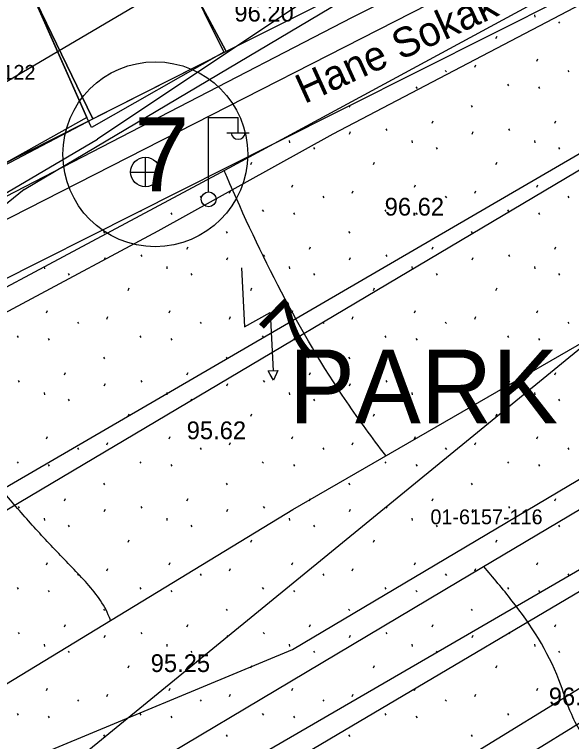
# Model space of a CAD drawing. Extents: x 412225 to 413380, y 4456471 to 4457189.
# Drawn here: x 412837.41 to 412875.09, y 4456673.13 to 4456722.27 of the extents above; entities that cross this region are included whole.
import ezdxf

# ---------------------------------------------------------------- set-up
doc = ezdxf.new("R2010")
doc.units = 0
for name, color, linetype in [('0_HALİHAZIR', 7, 'Continuous'), ('0_KADASTRO', 7, 'Continuous'), ('Level 28', 7, 'Continuous'), ('Level 41', 7, 'Continuous'), ('Level 54', 7, 'Continuous'), ('Level 58', 7, 'Continuous'), ('Level 62', 7, 'Continuous')]:
    doc.layers.add(name, color=color, linetype=linetype)

msp = doc.modelspace()

# ---------------------------------------------------------------- linework, layer by layer
at = {"layer": '0_HALİHAZIR'}
for p, q in [((412850.537, 4456710.308), (412850.537, 4456715.308)), ((412850.537, 4456715.308), (412852.537, 4456715.308)), ((412852.537, 4456714.308), (412852.537, 4456715.308)), ((412851.777, 4456714.268), (412853.277, 4456714.268)), ((412846.281, 4456710.619), (412846.281, 4456712.619)), ((412845.261, 4456711.609), (412847.261, 4456711.609))]:
    msp.add_line(p, q, dxfattribs=at)
for points in [[(413308.103, 4456965.941), (413265.175, 4456940.384), (413047.239, 4456812.664), (412821.475, 4456681.363)], [(412841.576, 4456665.003), (413057.926, 4456790.466), (413273.464, 4456916.652), (413307.769, 4456936.91)], [(412931.837, 4456800.178), (412903.863, 4456787.544), (412893.413, 4456782.904), (412892.513, 4456782.283), (412891.907, 4456781.457), (412891.837, 4456780.842), (412902.994, 4456756.704), (412906.93, 4456745.654), (412907.054, 4456744.017), (412906.977, 4456743.038), (412906.753, 4456742.155), (412906.55, 4456741.728), (412906.154, 4456741.055), (412879.555, 4456726.854), (412851.066, 4456711.433), (412824.165, 4456697.062), (412814.561, 4456691.644)], [(412816.025, 4456699.683), (412835.485, 4456709.295), (412860.277, 4456722.092), (412890.448, 4456737.159), (412902.212, 4456743.322), (412902.198, 4456743.87), (412894.314, 4456761.759), (412893.593, 4456762.996), (412893.507, 4456763.111), (412860.542, 4456748.553), (412831.808, 4456733.953), (412813.075, 4456726.17)], [(412858.966, 4456714.206), (412889.238, 4456730.065), (412907.414, 4456740.616), (412908.265, 4456741.87), (412908.952, 4456743.506), (412909.302, 4456744.253), (412909.611, 4456744.779), (412927.708, 4456755.383), (412944.2, 4456762.714), (412944.939, 4456762.704), (412945.604, 4456762.403), (412952.812, 4456743.534), (412954.202, 4456739.684), (412953.996, 4456738.954), (412951.842, 4456736.97)], [(412812.813, 4456662.398), (412856.245, 4456688.806), (412912.334, 4456721.138), (412944.097, 4456732.816)], [(412813.007, 4456650.071), (412835.489, 4456664.933), (412867.464, 4456683.962), (412901.181, 4456703.969), (412934.85, 4456721.065), (412956.754, 4456731.07), (412958.117, 4456731.459), (412959.035, 4456731.634), (412960.277, 4456731.39), (412961.32, 4456730.801), (412962.336, 4456729.858), (412972.363, 4456705.953), (412988.995, 4456670.284), (413003.917, 4456634.999), (413014.424, 4456609.495), (413014.707, 4456606.962), (413014.677, 4456605.697), (413014.483, 4456604.379), (413013.724, 4456603.316), (412984.218, 4456588.075)], [(412815.749, 4456691.343), (412828.75, 4456697.822), (412847.13, 4456707.658), (412858.966, 4456714.206)], [(412852.778, 4456705.155), (412852.971, 4456701.157), (412854.714, 4456702.136), (412854.91, 4456698.174)]]:
    msp.add_lwpolyline(points, dxfattribs=at)
for points in [[(412838.663, 4456723.568), (412847.549, 4456727.851), (412851.572, 4456719.726), (412842.627, 4456714.626), (412842.316, 4456715.307)], [(412838.188, 4456724.641), (412842.316, 4456715.307), (412833.98, 4456710.678), (412829.754, 4456719.226)], [(412854.574, 4456698.18), (412855.23, 4456698.217), (412854.931, 4456697.544), (412854.716, 4456697.928)]]:
    msp.add_lwpolyline(points, close=True, dxfattribs=at)
for centre, radius in [((412846.266, 4456711.627), 1), ((412850.548, 4456709.783), 0.5)]:
    msp.add_circle(centre, radius, dxfattribs=at)
msp.add_arc((412852.537, 4456714.311), 0.474, 184.8384, 355.1464, dxfattribs=at)
for points in [[(412862.546, 4456692.438), (412862.521, 4456692.47), (412859.884, 4456696.083), (412851.773, 4456711.318), (412851.599, 4456711.722)], [(412843.912, 4456681.307), (412843.757, 4456681.694), (412842.081, 4456684.075), (412840.012, 4456686.241), (412837.991, 4456688.456), (412836.059, 4456690.749), (412834.248, 4456693.133), (412832.578, 4456695.619), (412831.011, 4456698.177), (412829.858, 4456700.104)], [(412954.779, 4456612.553), (412952.206, 4456613.697), (412941.009, 4456618.727), (412920.288, 4456630.573), (412911.175, 4456637.709), (412908.09, 4456640.597), (412896.792, 4456650.717), (412890.704, 4456656.374), (412889.418, 4456657.685), (412876.396, 4456672.773), (412875.794, 4456673.634), (412875.1, 4456674.94), (412874.235, 4456677.292), (412871.061, 4456682.644), (412869.151, 4456684.963)]]:
    msp.add_spline(points, degree=3, dxfattribs=at)
at = {"layer": '0_KADASTRO'}
for points in [[(412758.558, 4456668.786), (412808.977, 4456694.209), (412902.634, 4456741.974), (412909.074, 4456745.179), (412943.419, 4456762.272), (412949.024, 4456765.062), (412952.615, 4456766.849), (412963.581, 4456772.307), (412985.511, 4456783.221), (412985.536, 4456782.611), (412987.65, 4456731.4), (412981.45, 4456727.59), (412970.633, 4456720.947), (412967.171, 4456718.821), (412964.24, 4456717.02), (412920.19, 4456689.98), (412911.66, 4456684.75), (412892.499, 4456672.986), (412877.7, 4456663.9), (412867.363, 4456657.565), (412824.012, 4456630.971), (412807.183, 4456620.644)], [(412846.893, 4456728.773), (412852.747, 4456731.593), (412855.714, 4456733.022), (412860.243, 4456724.055), (412851.736, 4456719.768), (412851.687, 4456719.86), (412847.536, 4456727.578)], [(412838.173, 4456724.573), (412840.926, 4456725.899), (412846.893, 4456728.773), (412847.536, 4456727.578), (412851.687, 4456719.86), (412851.736, 4456719.768), (412842.722, 4456715.224), (412842.675, 4456715.32), (412838.877, 4456723.125)], [(412829.278, 4456720.289), (412834.972, 4456723.032), (412838.173, 4456724.573), (412838.877, 4456723.125), (412842.675, 4456715.32), (412842.722, 4456715.224), (412834.005, 4456710.64), (412833.943, 4456710.767), (412829.896, 4456719.028)]]:
    msp.add_lwpolyline(points, close=True, dxfattribs=at)
at = {"layer": 'Level 28'}
for p, q in [((412901.361, 4456744.693), (412851.736, 4456719.768)), ((412854.878, 4456713.513), (412901.65, 4456737.005)), ((412851.736, 4456719.768), (412806.83, 4456697.135)), ((412803.636, 4456687.687), (412854.887, 4456713.517)), ((412917.79, 4456702.575), (412795.286, 4456627.414))]:
    msp.add_line(p, q, dxfattribs=at)
at = {"layer": 'Level 41'}
for p, q in [((412872.587, 4456722.26), (412872.605, 4456722.1)), ((412874.217, 4456721.79), (412874.287, 4456721.683)), ((412869.98, 4456720.646), (412870.052, 4456720.806)), ((412872.752, 4456719.116), (412872.822, 4456719.276)), ((412866.554, 4456718.5), (412866.625, 4456718.394)), ((412868.542, 4456718.708), (412868.613, 4456718.868)), ((412874.847, 4456718.5), (412874.918, 4456718.394)), ((412870.762, 4456717.571), (412870.833, 4456717.464)), ((412864.568, 4456717.379), (412864.639, 4456717.272)), ((412872.861, 4456717.379), (412872.932, 4456717.272)), ((412860.026, 4456716.098), (412860.084, 4456716.011)), ((412868.306, 4456716.118), (412868.377, 4456716.011)), ((412865.665, 4456714.925), (412865.736, 4456715.084)), ((412873.958, 4456714.925), (412874.029, 4456715.084)), ((412862.536, 4456714.541), (412862.607, 4456714.434)), ((412870.829, 4456714.541), (412870.9, 4456714.434)), ((412860.071, 4456714.196), (412860.143, 4456714.356)), ((412868.364, 4456714.196), (412868.436, 4456714.356)), ((412856.001, 4456713.75), (412856.019, 4456713.59)), ((412864.294, 4456713.75), (412864.312, 4456713.59)), ((412872.587, 4456713.75), (412872.605, 4456713.59)), ((412857.631, 4456713.28), (412857.701, 4456713.173)), ((412865.924, 4456713.28), (412865.994, 4456713.173)), ((412874.217, 4456713.28), (412874.287, 4456713.173)), ((412853.394, 4456712.136), (412853.466, 4456712.296)), ((412861.687, 4456712.136), (412861.759, 4456712.296)), ((412869.98, 4456712.136), (412870.052, 4456712.296)), ((412856.166, 4456710.606), (412856.236, 4456710.766)), ((412864.459, 4456710.606), (412864.529, 4456710.766)), ((412872.752, 4456710.606), (412872.822, 4456710.766)), ((412851.956, 4456710.198), (412852.027, 4456710.358)), ((412860.249, 4456710.198), (412860.32, 4456710.358)), ((412868.542, 4456710.198), (412868.613, 4456710.358)), ((412849.968, 4456709.99), (412850.039, 4456709.884)), ((412858.261, 4456709.99), (412858.332, 4456709.884)), ((412866.554, 4456709.99), (412866.625, 4456709.884)), ((412874.847, 4456709.99), (412874.918, 4456709.884)), ((412854.176, 4456709.061), (412854.247, 4456708.954)), ((412862.469, 4456709.061), (412862.54, 4456708.954)), ((412870.762, 4456709.061), (412870.833, 4456708.954)), ((412845.924, 4456709), (412845.954, 4456708.954)), ((412847.982, 4456708.869), (412848.053, 4456708.762)), ((412856.275, 4456708.869), (412856.346, 4456708.762)), ((412864.568, 4456708.869), (412864.639, 4456708.762)), ((412872.861, 4456708.869), (412872.932, 4456708.762)), ((412843.427, 4456707.608), (412843.498, 4456707.501)), ((412851.72, 4456707.608), (412851.791, 4456707.501)), ((412860.013, 4456707.608), (412860.084, 4456707.501)), ((412868.306, 4456707.608), (412868.377, 4456707.501)), ((412849.079, 4456706.415), (412849.15, 4456706.574)), ((412857.372, 4456706.415), (412857.443, 4456706.574)), ((412865.665, 4456706.415), (412865.736, 4456706.574)), ((412873.958, 4456706.415), (412874.029, 4456706.574)), ((412843.485, 4456705.686), (412843.557, 4456705.846)), ((412845.95, 4456706.031), (412846.021, 4456705.924)), ((412851.778, 4456705.686), (412851.85, 4456705.846)), ((412854.243, 4456706.031), (412854.314, 4456705.924)), ((412860.071, 4456705.686), (412860.143, 4456705.846)), ((412862.536, 4456706.031), (412862.607, 4456705.924)), ((412868.364, 4456705.686), (412868.436, 4456705.846)), ((412870.829, 4456706.031), (412870.9, 4456705.924)), ((412839.415, 4456705.24), (412839.433, 4456705.08)), ((412847.708, 4456705.24), (412847.726, 4456705.08)), ((412856.001, 4456705.24), (412856.019, 4456705.08)), ((412864.294, 4456705.24), (412864.312, 4456705.08)), ((412872.587, 4456705.24), (412872.605, 4456705.08)), ((412841.045, 4456704.77), (412841.115, 4456704.663)), ((412849.338, 4456704.77), (412849.408, 4456704.663)), ((412857.631, 4456704.77), (412857.701, 4456704.663)), ((412865.924, 4456704.77), (412865.994, 4456704.663)), ((412874.217, 4456704.77), (412874.287, 4456704.663)), ((412845.101, 4456703.626), (412845.173, 4456703.786)), ((412853.394, 4456703.626), (412853.466, 4456703.786)), ((412861.687, 4456703.626), (412861.759, 4456703.786)), ((412869.98, 4456703.626), (412870.052, 4456703.786)), ((412839.58, 4456702.096), (412839.65, 4456702.256)), ((412847.873, 4456702.096), (412847.943, 4456702.256)), ((412856.166, 4456702.096), (412856.236, 4456702.256)), ((412864.459, 4456702.096), (412864.529, 4456702.256)), ((412872.752, 4456702.096), (412872.822, 4456702.256)), ((412843.663, 4456701.688), (412843.734, 4456701.848)), ((412851.956, 4456701.688), (412852.027, 4456701.848)), ((412860.249, 4456701.688), (412860.32, 4456701.848)), ((412868.542, 4456701.688), (412868.613, 4456701.848)), ((412841.675, 4456701.48), (412841.746, 4456701.374)), ((412849.968, 4456701.48), (412850.039, 4456701.374)), ((412858.261, 4456701.48), (412858.332, 4456701.374)), ((412866.554, 4456701.48), (412866.625, 4456701.374)), ((412874.847, 4456701.48), (412874.918, 4456701.374)), ((412837.59, 4456700.551), (412837.661, 4456700.444)), ((412839.689, 4456700.359), (412839.76, 4456700.252)), ((412845.883, 4456700.551), (412845.954, 4456700.444)), ((412847.982, 4456700.359), (412848.053, 4456700.252)), ((412854.176, 4456700.551), (412854.247, 4456700.444)), ((412856.275, 4456700.359), (412856.346, 4456700.252)), ((412862.469, 4456700.551), (412862.54, 4456700.444)), ((412864.568, 4456700.359), (412864.639, 4456700.252)), ((412870.762, 4456700.551), (412870.833, 4456700.444)), ((412872.861, 4456700.359), (412872.932, 4456700.252)), ((412843.427, 4456699.098), (412843.498, 4456698.991)), ((412851.72, 4456699.098), (412851.791, 4456698.991)), ((412860.013, 4456699.098), (412860.084, 4456698.991)), ((412868.306, 4456699.098), (412868.377, 4456698.991)), ((412840.786, 4456697.905), (412840.857, 4456698.064)), ((412849.079, 4456697.905), (412849.15, 4456698.064)), ((412857.372, 4456697.905), (412857.443, 4456698.064)), ((412865.665, 4456697.905), (412865.736, 4456698.064)), ((412873.958, 4456697.905), (412874.029, 4456698.064)), ((412837.657, 4456697.521), (412837.728, 4456697.414)), ((412843.485, 4456697.176), (412843.557, 4456697.336)), ((412845.95, 4456697.521), (412846.021, 4456697.414)), ((412851.778, 4456697.176), (412851.85, 4456697.336)), ((412854.243, 4456697.521), (412854.314, 4456697.414)), ((412860.071, 4456697.176), (412860.143, 4456697.336)), ((412862.536, 4456697.521), (412862.607, 4456697.414)), ((412868.364, 4456697.176), (412868.436, 4456697.336)), ((412870.829, 4456697.521), (412870.9, 4456697.414)), ((412839.415, 4456696.73), (412839.433, 4456696.57)), ((412847.708, 4456696.73), (412847.726, 4456696.57)), ((412856.001, 4456696.73), (412856.019, 4456696.57)), ((412864.294, 4456696.73), (412864.312, 4456696.57)), ((412872.587, 4456696.73), (412872.605, 4456696.57)), ((412841.045, 4456696.26), (412841.115, 4456696.153)), ((412849.338, 4456696.26), (412849.408, 4456696.153)), ((412857.631, 4456696.26), (412857.701, 4456696.153)), ((412865.924, 4456696.26), (412865.994, 4456696.153)), ((412874.217, 4456696.26), (412874.287, 4456696.153)), ((412845.101, 4456695.116), (412845.173, 4456695.276)), ((412853.394, 4456695.116), (412853.466, 4456695.276)), ((412861.687, 4456695.116), (412861.759, 4456695.276)), ((412869.98, 4456695.116), (412870.052, 4456695.276)), ((412839.58, 4456693.586), (412839.65, 4456693.746)), ((412843.663, 4456693.178), (412843.734, 4456693.338)), ((412847.873, 4456693.586), (412847.943, 4456693.746)), ((412851.956, 4456693.178), (412852.027, 4456693.338)), ((412856.166, 4456693.586), (412856.236, 4456693.746)), ((412860.249, 4456693.178), (412860.32, 4456693.338)), ((412864.459, 4456693.586), (412864.529, 4456693.746)), ((412868.542, 4456693.178), (412868.613, 4456693.338)), ((412872.752, 4456693.586), (412872.822, 4456693.746)), ((412841.675, 4456692.97), (412841.746, 4456692.864)), ((412849.968, 4456692.97), (412850.039, 4456692.864)), ((412858.261, 4456692.97), (412858.332, 4456692.864)), ((412866.554, 4456692.97), (412866.625, 4456692.864)), ((412874.847, 4456692.97), (412874.918, 4456692.864)), ((412837.59, 4456692.041), (412837.661, 4456691.934)), ((412839.689, 4456691.849), (412839.76, 4456691.742)), ((412845.883, 4456692.041), (412845.954, 4456691.934)), ((412847.982, 4456691.849), (412848.053, 4456691.742)), ((412854.176, 4456692.041), (412854.247, 4456691.934)), ((412856.275, 4456691.849), (412856.346, 4456691.742)), ((412862.469, 4456692.041), (412862.54, 4456691.934)), ((412864.568, 4456691.849), (412864.639, 4456691.742)), ((412870.762, 4456692.041), (412870.833, 4456691.934)), ((412872.861, 4456691.849), (412872.932, 4456691.742)), ((412843.427, 4456690.588), (412843.498, 4456690.481)), ((412851.72, 4456690.588), (412851.791, 4456690.481)), ((412860.013, 4456690.588), (412860.084, 4456690.481)), ((412868.306, 4456690.588), (412868.377, 4456690.481)), ((412840.786, 4456689.395), (412840.857, 4456689.554)), ((412849.079, 4456689.395), (412849.15, 4456689.554)), ((412857.372, 4456689.395), (412857.443, 4456689.554)), ((412865.665, 4456689.395), (412865.736, 4456689.554)), ((412873.958, 4456689.395), (412874.029, 4456689.554)), ((412837.657, 4456689.011), (412837.728, 4456688.904)), ((412845.95, 4456689.011), (412846.021, 4456688.904)), ((412854.243, 4456689.011), (412854.314, 4456688.904)), ((412862.536, 4456689.011), (412862.607, 4456688.904)), ((412870.829, 4456689.011), (412870.9, 4456688.904)), ((412843.485, 4456688.666), (412843.557, 4456688.826)), ((412851.778, 4456688.666), (412851.85, 4456688.826)), ((412860.071, 4456688.666), (412860.143, 4456688.826)), ((412868.364, 4456688.666), (412868.436, 4456688.826)), ((412839.415, 4456688.22), (412839.433, 4456688.06)), ((412847.708, 4456688.22), (412847.726, 4456688.06)), ((412856.001, 4456688.22), (412856.019, 4456688.06)), ((412864.294, 4456688.22), (412864.312, 4456688.06)), ((412872.587, 4456688.22), (412872.605, 4456688.06)), ((412841.045, 4456687.75), (412841.115, 4456687.643)), ((412849.338, 4456687.75), (412849.408, 4456687.643)), ((412857.631, 4456687.75), (412857.701, 4456687.643)), ((412865.924, 4456687.75), (412865.994, 4456687.643)), ((412874.217, 4456687.75), (412874.287, 4456687.643)), ((412845.101, 4456686.606), (412845.173, 4456686.766)), ((412853.394, 4456686.606), (412853.466, 4456686.766)), ((412861.687, 4456686.606), (412861.759, 4456686.766)), ((412869.98, 4456686.606), (412870.052, 4456686.766)), ((412839.58, 4456685.076), (412839.65, 4456685.236)), ((412847.873, 4456685.076), (412847.943, 4456685.236)), ((412856.166, 4456685.076), (412856.236, 4456685.236)), ((412864.459, 4456685.076), (412864.529, 4456685.236)), ((412872.752, 4456685.076), (412872.822, 4456685.236)), ((412843.663, 4456684.668), (412843.734, 4456684.828)), ((412851.956, 4456684.668), (412852.027, 4456684.828)), ((412860.249, 4456684.668), (412860.32, 4456684.828)), ((412868.542, 4456684.668), (412868.613, 4456684.828)), ((412841.675, 4456684.46), (412841.746, 4456684.354)), ((412849.968, 4456684.46), (412850.039, 4456684.354)), ((412858.261, 4456684.46), (412858.332, 4456684.354)), ((412866.554, 4456684.46), (412866.625, 4456684.354)), ((412874.847, 4456684.46), (412874.918, 4456684.354)), ((412837.59, 4456683.531), (412837.661, 4456683.424)), ((412845.883, 4456683.531), (412845.954, 4456683.424)), ((412854.176, 4456683.531), (412854.247, 4456683.424)), ((412862.469, 4456683.531), (412862.54, 4456683.424)), ((412870.762, 4456683.531), (412870.833, 4456683.424)), ((412839.689, 4456683.339), (412839.76, 4456683.232)), ((412847.982, 4456683.339), (412848.053, 4456683.232)), ((412856.275, 4456683.339), (412856.346, 4456683.232)), ((412864.568, 4456683.339), (412864.639, 4456683.232)), ((412872.861, 4456683.339), (412872.932, 4456683.232)), ((412843.427, 4456682.078), (412843.498, 4456681.971)), ((412851.72, 4456682.078), (412851.791, 4456681.971)), ((412860.013, 4456682.078), (412860.084, 4456681.971)), ((412868.306, 4456682.078), (412868.377, 4456681.971)), ((412840.786, 4456680.885), (412840.857, 4456681.044)), ((412849.079, 4456680.885), (412849.15, 4456681.044)), ((412857.372, 4456680.885), (412857.443, 4456681.044)), ((412865.665, 4456680.885), (412865.736, 4456681.044)), ((412873.958, 4456680.885), (412874.029, 4456681.044)), ((412837.657, 4456680.501), (412837.728, 4456680.394)), ((412843.485, 4456680.156), (412843.557, 4456680.316)), ((412845.95, 4456680.501), (412846.021, 4456680.394)), ((412851.778, 4456680.156), (412851.85, 4456680.316)), ((412854.243, 4456680.501), (412854.314, 4456680.394)), ((412860.071, 4456680.156), (412860.143, 4456680.316)), ((412862.536, 4456680.501), (412862.607, 4456680.394)), ((412868.364, 4456680.156), (412868.436, 4456680.316)), ((412870.829, 4456680.501), (412870.9, 4456680.394)), ((412839.415, 4456679.71), (412839.433, 4456679.55)), ((412847.708, 4456679.71), (412847.726, 4456679.55)), ((412856.001, 4456679.71), (412856.019, 4456679.55)), ((412864.294, 4456679.71), (412864.312, 4456679.55)), ((412872.587, 4456679.71), (412872.605, 4456679.55)), ((412841.045, 4456679.24), (412841.115, 4456679.133)), ((412849.338, 4456679.24), (412849.408, 4456679.133)), ((412857.631, 4456679.24), (412857.701, 4456679.133)), ((412865.924, 4456679.24), (412865.994, 4456679.133)), ((412874.217, 4456679.24), (412874.287, 4456679.133)), ((412845.101, 4456678.096), (412845.173, 4456678.256)), ((412853.394, 4456678.096), (412853.466, 4456678.256)), ((412861.687, 4456678.096), (412861.759, 4456678.256)), ((412869.98, 4456678.096), (412870.052, 4456678.256)), ((412839.58, 4456676.566), (412839.65, 4456676.726)), ((412847.873, 4456676.566), (412847.943, 4456676.726)), ((412856.166, 4456676.566), (412856.236, 4456676.726)), ((412864.459, 4456676.566), (412864.529, 4456676.726)), ((412872.752, 4456676.566), (412872.822, 4456676.726)), ((412843.663, 4456676.158), (412843.734, 4456676.318)), ((412851.956, 4456676.158), (412852.027, 4456676.318)), ((412860.249, 4456676.158), (412860.32, 4456676.318)), ((412868.542, 4456676.158), (412868.613, 4456676.318)), ((412841.675, 4456675.95), (412841.746, 4456675.844)), ((412849.968, 4456675.95), (412850.039, 4456675.844)), ((412858.261, 4456675.95), (412858.332, 4456675.844)), ((412866.554, 4456675.95), (412866.625, 4456675.844)), ((412837.59, 4456675.021), (412837.661, 4456674.914)), ((412839.689, 4456674.829), (412839.76, 4456674.722)), ((412845.883, 4456675.021), (412845.954, 4456674.914)), ((412847.982, 4456674.829), (412848.053, 4456674.722)), ((412854.176, 4456675.021), (412854.247, 4456674.914)), ((412856.275, 4456674.829), (412856.346, 4456674.722)), ((412862.469, 4456675.021), (412862.54, 4456674.914)), ((412864.568, 4456674.829), (412864.639, 4456674.722)), ((412870.762, 4456675.021), (412870.833, 4456674.914)), ((412843.427, 4456673.568), (412843.498, 4456673.461)), ((412851.72, 4456673.568), (412851.791, 4456673.461)), ((412860.013, 4456673.568), (412860.084, 4456673.461)), ((412868.306, 4456673.568), (412868.377, 4456673.461))]:
    msp.add_line(p, q, dxfattribs=at)
at = {"layer": 'Level 54'}
for p, q in [((412879.336, 4456738.107), (412843.025, 4456713.837)), ((412838.075, 4456710.447), (412777.393, 4456661.653)), ((412839.084, 4456669.826), (412887.855, 4456709.671)), ((412784.448, 4456649.562), (412856.216, 4456679.35))]:
    msp.add_line(p, q, dxfattribs=at)
for points in [[(412772.861, 4456680.089), (413040.614, 4456837.658)], [(412772.521, 4456650.705), (412780.988, 4456655.646), (413046.364, 4456813.097)], [(412842.641, 4456663.797), (413057.204, 4456790.554)], [(412838.075, 4456710.447), (412970.517, 4456789.026)], [(412856.216, 4456679.35), (412988.664, 4456757.933)], [(412776.158, 4456674.487), (412843.025, 4456713.837)]]:
    msp.add_lwpolyline(points, dxfattribs=at)
at = {"layer": 'Level 58'}
msp.add_circle((412846.934, 4456712.827), 6.25, dxfattribs=at)
at = {"layer": 'Level 62'}
msp.add_line((412921.393, 4456702.44), (412819.706, 4456640.05), dxfattribs=at)

# ---------------------------------------------------------------- texts
at = {"layer": '0_HALİHAZIR'}
msp.add_text('Hane Sokak', height=2, rotation=24.483, dxfattribs=at).set_placement((412857.021, 4456716.212))
for s, p in [('96.20', (412852.286, 4456721.8)), ('96.62', (412862.452, 4456708.68)), ('95.62', (412849.061, 4456693.562)), ('95.25', (412846.625, 4456677.821)), ('96.05', (412873.552, 4456675.567))]:
    msp.add_text(s, height=1.2, dxfattribs=at).set_placement(p)
at = {"layer": '0_KADASTRO'}
for s, p in [('01-6157-122', (412831.245, 4456717.863)), ('01-6157-122', (412831.245, 4456717.863)), ('01-6157-116', (412865.547, 4456687.814)), ('01-6157-116', (412865.547, 4456687.814))]:
    msp.add_text(s, height=1, dxfattribs=at).set_placement(p)
at = {"layer": 'Level 28'}
msp.add_text('PARK', height=5, dxfattribs=at).set_placement((412855.98, 4456694.625))
at = {"layer": 'Level 54'}
msp.add_text('7', height=4, rotation=45.5609, dxfattribs=at).set_placement((412856.624, 4456698.342))
at = {"layer": 'Level 58'}
msp.add_text('7', height=5, dxfattribs=at).set_placement((412845.516, 4456710.327))

doc.saveas('drawing.dxf')
